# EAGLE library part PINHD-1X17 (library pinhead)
PIN HEADER
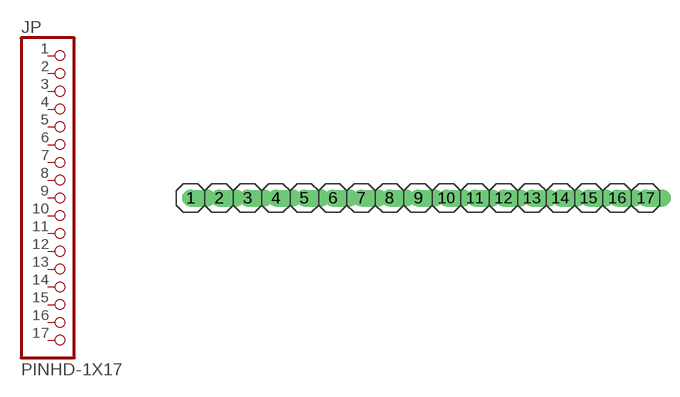
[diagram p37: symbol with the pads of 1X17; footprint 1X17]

Designator prefix JP

## PINHD-1X17  [1X17]
1  1  pas
2  2  pas
3  3  pas
4  4  pas
5  5  pas
6  6  pas
7  7  pas
8  8  pas
9  9  pas
10  10  pas
11  11  pas
12  12  pas
13  13  pas
14  14  pas
15  15  pas
16  16  pas
17  17  pas

## Footprint 1X17 (pad centres in mm)
PIN HEADER
drill 1.016 offset: 1 -20.32,0; 2 -17.78,0; 3 -15.24,0; 4 -12.7,0; 5 -10.16,0; 6 -7.62,0; 7 -5.08,0; 8 -2.54,0; 9 0,0; 10 2.54,0; 11 5.08,0; 12 7.62,0; 13 10.16,0; 14 12.7,0; 15 15.24,0; 16 17.78,0; 17 20.32,0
